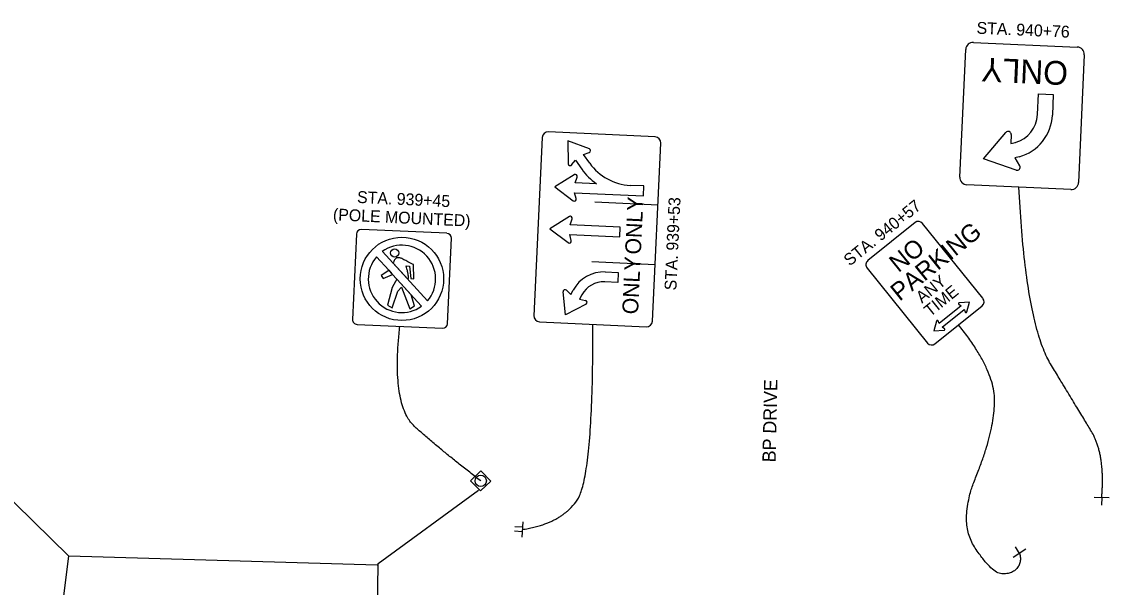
# Model space of a CAD drawing. Extents: x 1847379 to 1850904, y 217032 to 220169.
# Drawn here: x 1847990 to 1848218.9, y 218932.5 to 219051.5 of the extents above; entities that cross this region are included whole.
import ezdxf

# ---------------------------------------------------------------- set-up
doc = ezdxf.new("R2010")
doc.units = 0
for name, color, linetype in [('SG_X_Wiring', 7, 'Continuous'), ('SN_X_Foundation', 7, 'Continuous'), ('SN_X_Public', 7, 'Continuous'), ('SN_X_Text', 7, 'Continuous')]:
    doc.layers.add(name, color=color, linetype=linetype)

msp = doc.modelspace()

# ---------------------------------------------------------------- linework, layer by layer
at = {"layer": 'SG_X_Wiring'}
for p, q in [((1847999.88, 218939.03), (1847980.01, 218958.48)), ((1848065.02, 218937.49), (1848086.09, 218952.89)), ((1847991.33, 218868.98), (1847999.88, 218939.03)), ((1848064.78, 218937.13), (1847999.88, 218939.03)), ((1848063.94, 218866.48), (1848065.02, 218937.49))]:
    msp.add_line(p, q, dxfattribs=at)
at = {"layer": 'SN_X_Foundation'}
msp.add_lwpolyline([(1848086.54, 218952.73), (1848088.7, 218954.81), (1848086.62, 218956.97), (1848084.46, 218954.89)], close=True, dxfattribs=at)
msp.add_circle((1848086.58, 218954.85), 1.2, dxfattribs=at)
at = {"layer": 'SN_X_Public'}
for p, q in [((1848203.76, 219031.92), (1848203.96, 219036.29)), ((1848203.96, 219036.29), (1848207.08, 219036.15)), ((1848207.08, 219036.15), (1848206.88, 219031.78)), ((1848192.39, 219022.63), (1848197.1, 219028.17)), ((1848198.2, 219027.74), (1848198.13, 219025.81)), ((1848109.45, 219024.74), (1848104.91, 219026.4)), ((1848104.91, 219026.4), (1848104.98, 219021.57)), ((1848198.13, 219025.81), (1848199.09, 219026.07)), ((1848108.21, 219023.55), (1848109.43, 219023.95)), ((1848109.53, 219021.68), (1848108.21, 219023.55)), ((1848105.72, 219021.32), (1848106.51, 219022.35)), ((1848106.51, 219022.35), (1848107.83, 219020.47)), ((1848199.26, 219020.24), (1848192.39, 219022.63)), ((1848199.91, 219023.06), (1848198.95, 219022.8)), ((1848198.95, 219022.8), (1848200, 219021.17)), ((1848106.27, 219019.28), (1848102.16, 219016.73)), ((1848106.44, 219017.57), (1848106.88, 219018.78)), ((1848102.16, 219016.73), (1848106.01, 219013.81)), ((1848110.94, 219017.36), (1848106.44, 219017.57)), ((1848120.94, 219016.9), (1848118.03, 219017.03)), ((1848120.84, 219014.81), (1848120.94, 219016.9)), ((1848106.67, 219014.25), (1848106.34, 219015.49)), ((1848106.34, 219015.49), (1848120.84, 219014.81)), ((1848110.57, 219013.57), (1848123.89, 219012.95)), ((1848105.23, 219010.47), (1848101.13, 219007.92)), ((1848105.4, 219008.76), (1848105.84, 219009.97)), ((1848101.13, 219007.92), (1848104.98, 219004.99)), ((1848115.95, 219008.26), (1848105.4, 219008.76)), ((1848115.85, 219006.18), (1848115.95, 219008.26)), ((1848105.63, 219005.43), (1848105.3, 219006.68)), ((1848105.3, 219006.68), (1848115.85, 219006.18)), ((1848065.88, 219003.13), (1848075.37, 218992.73)), ((1848068.11, 219000.68), (1848068.21, 219000.57)), ((1848068.21, 219000.57), (1848071.28, 218997.21)), ((1848072.41, 219000.38), (1848072.39, 219000.38)), ((1848072.41, 219000.38), (1848072.39, 219000.38)), ((1848072.5, 218997.39), (1848072.41, 219000.38)), ((1848072.5, 218997.39), (1848072.41, 219000.38)), ((1848109.98, 219000.98), (1848123.3, 219000.36)), ((1848067.25, 218999.13), (1848065.65, 218998.05)), ((1848067.25, 218999.13), (1848065.65, 218998.05)), ((1848065.65, 218998.05), (1848066.03, 218997.45)), ((1848065.65, 218998.05), (1848066.03, 218997.45)), ((1848066.03, 218997.45), (1848068.03, 218998.27)), ((1848066.03, 218997.45), (1848068.03, 218998.27)), ((1848068.03, 218998.27), (1848067.88, 218998.44)), ((1848070.88, 219000.08), (1848071.61, 219000.02)), ((1848070.88, 219000.08), (1848071.61, 219000.02)), ((1848071.61, 219000.02), (1848071.87, 218997.47)), ((1848071.61, 219000.02), (1848071.87, 218997.47)), ((1848112.8, 218998.82), (1848115.5, 218998.69)), ((1848115.5, 218998.69), (1848115.41, 218996.61)), ((1848068.62, 218996.82), (1848067.97, 218995.56)), ((1848068.62, 218996.82), (1848067.97, 218995.56)), ((1848068.91, 218997.31), (1848068.62, 218996.82)), ((1848068.91, 218997.31), (1848068.62, 218996.82)), ((1848068.97, 218997.25), (1848068.91, 218997.31)), ((1848071.92, 218994.03), (1848068.97, 218997.25)), ((1848071.87, 218997.47), (1848072.5, 218997.39)), ((1848071.87, 218997.47), (1848072.5, 218997.39)), ((1848115.41, 218996.61), (1848112.7, 218996.74)), ((1848067.97, 218995.56), (1848066.96, 218991.82)), ((1848067.97, 218995.56), (1848066.96, 218991.82)), ((1848067.97, 218991.27), (1848069.17, 218994.74)), ((1848067.97, 218991.27), (1848069.17, 218994.74)), ((1848069.17, 218994.74), (1848069.93, 218995.61)), ((1848069.17, 218994.74), (1848069.93, 218995.61)), ((1848069.93, 218995.61), (1848071.69, 218991.02)), ((1848069.93, 218995.61), (1848071.69, 218991.02)), ((1848072.61, 218991.65), (1848071.92, 218994.03)), ((1848072.61, 218991.65), (1848071.92, 218994.03)), ((1848104.45, 218989.82), (1848103.92, 218994.63)), ((1848104.63, 218994.97), (1848105.53, 218994.05)), ((1848105.53, 218994.05), (1848106.03, 218994.98)), ((1848107.86, 218993.99), (1848107.37, 218993.06)), ((1848066.96, 218991.82), (1848067.97, 218991.27)), ((1848066.96, 218991.82), (1848067.97, 218991.27)), ((1848071.69, 218991.02), (1848072.61, 218991.65)), ((1848071.69, 218991.02), (1848072.61, 218991.65)), ((1848108.75, 218992.04), (1848104.45, 218989.82)), ((1848107.37, 218993.06), (1848108.63, 218992.82)), ((1848187.71, 218991.67), (1848183.08, 218987.94)), ((1848187.22, 218992.01), (1848187.72, 218991.68)), ((1848189.47, 218992.48), (1848187.31, 218992.34)), ((1848187.72, 218991.68), (1848187.71, 218991.67)), ((1848188.87, 218990.4), (1848189.47, 218992.48)), ((1848185.7, 218989.44), (1848185.7, 218989.44)), ((1848188.31, 218990.95), (1848188.52, 218990.39)), ((1848182.52, 218988.48), (1848181.92, 218986.4)), ((1848181.92, 218986.4), (1848184.08, 218986.55)), ((1848183.08, 218987.94), (1848182.87, 218988.5)), ((1848183.08, 218987.94), (1848183.09, 218987.94)), ((1848184.17, 218986.88), (1848183.67, 218987.21)), ((1848215.66, 218951.41), (1848218.85, 218951.33)), ((1848217.26, 218951.37), (1848217.21, 218949.77)), ((1848095.42, 218946.22), (1848095.23, 218943.03)), ((1848095.3, 218944.15), (1848093.7, 218944.24)), ((1848095.36, 218945.1), (1848093.76, 218945.2)), ((1848095.33, 218944.63), (1848095.33, 218944.63)), ((1848199.97, 218939.61), (1848199.1, 218940.95)), ((1848201.31, 218940.48), (1848198.63, 218938.74))]:
    msp.add_line(p, q, dxfattribs=at)
for points in [[(1848190.27, 219047.12), (1848212.12, 219046.14)], [(1848187.42, 219018.79), (1848188.64, 219045.63)], [(1848213.61, 219044.51), (1848212.4, 219017.66)], [(1848123.3, 219027.21), (1848100.83, 219028.26)], [(1848099.52, 219027.07), (1848097.77, 218989.61)], [(1848122.74, 218988.45), (1848124.49, 219025.91)], [(1848210.77, 219016.17), (1848188.91, 219017.16)], [(1848079.44, 219006.94), (1848061.46, 219007.75)], [(1848177.99, 219009.21), (1848168.06, 219001.21)], [(1848192.28, 218993.27), (1848179.57, 219009.04)], [(1848060.42, 219006.79), (1848059.61, 218988.81)], [(1848079.59, 218987.91), (1848080.4, 219005.89)], [(1848064.63, 219001.99), (1848067.21, 218999.17), (1848067.88, 218998.45), (1848067.88, 218998.44)], [(1848068.21, 219000.57), (1848068.21, 219000.57)], [(1848067.88, 218998.44), (1848067.25, 218999.13), (1848067.25, 218999.13)], [(1848067.88, 218998.44), (1848068.97, 218997.25), (1848072.51, 218993.38), (1848074.14, 218991.6)], [(1848167.89, 218999.62), (1848180.6, 218983.86)], [(1848182.18, 218983.69), (1848192.11, 218991.69)], [(1848183.67, 218987.21), (1848188.3, 218990.94)], [(1848060.56, 218987.77), (1848078.55, 218986.96)], [(1848098.96, 218988.31), (1848121.43, 218987.26)]]:
    msp.add_lwpolyline(points, dxfattribs=at)
for centre, radius in [((1848070, 218997.36), 8.77), ((1848068.47, 219002.81), 0.864)]:
    msp.add_circle(centre, radius, dxfattribs=at)
for centre, radius, start, end in [((1848190.2, 219045.56), 1.56, 87.4125, 177.4125), ((1848212.05, 219044.58), 1.56, 357.4125, 87.4125), ((1848197.41, 219032.2), 6.35, 285.2738, 357.4125), ((1848197.41, 219032.2), 9.48, 285.2699, 357.4125), ((1848100.77, 219027.02), 1.25, 87.3236, 177.3236), ((1848197.58, 219027.77), 0.625, 357.8864, 139.6582), ((1848123.24, 219025.96), 1.25, 357.3236, 87.3236), ((1848109.3, 219024.35), 0.417, 287.9475, 69.8256), ((1848105.39, 219021.58), 0.417, 180.7931, 322.6712), ((1848118.54, 219028.06), 11.04, 215.3093, 267.3236), ((1848199.47, 219020.83), 0.625, 250.8471, 32.6189), ((1848106.49, 219018.93), 0.417, 339.9618, 121.8399), ((1848118.54, 219028.06), 13.12, 215.3093, 234.5981), ((1848188.98, 219018.72), 1.56, 177.4125, 267.4125), ((1848210.84, 219017.73), 1.56, 267.4125, 357.4125), ((1848106.27, 219014.14), 0.417, 232.8074, 14.6855), ((1848105.45, 219010.11), 0.417, 339.9618, 121.8399), ((1848178.7, 219008.33), 1.12, 38.8676, 128.8676), ((1848061.42, 219006.75), 1, 87.4245, 177.4245), ((1848079.4, 219005.94), 1, 357.4245, 87.4245), ((1848105.23, 219005.32), 0.417, 232.8074, 14.6855), ((1848070, 218997.36), 7.09, 319.2436, 125.5959), ((1848070, 218997.36), 7.09, 139.2725, 305.6725), ((1848070, 218997.36), 7.09, 139.2725, 305.6725), ((1848168.77, 219000.33), 1.12, 128.8676, 218.8676), ((1848112.46, 218991.53), 7.29, 87.3236, 151.8409), ((1848112.46, 218991.53), 5.21, 87.3236, 151.8409), ((1848104.33, 218994.67), 0.417, 44.4791, 186.3572), ((1848108.55, 218992.41), 0.417, 297.3247, 79.2028), ((1848187.32, 218992.16), 0.182, 93.7884, 236.5054), ((1848191.4, 218992.56), 1.12, 308.8676, 38.8676), ((1848099.02, 218989.56), 1.25, 177.3236, 267.3236), ((1848188.69, 218990.45), 0.182, 201.2298, 343.9469), ((1848060.61, 218988.77), 1, 177.4245, 267.4245), ((1848078.59, 218987.96), 1, 267.4245, 357.4245), ((1848121.49, 218988.51), 1.25, 267.3236, 357.3236), ((1848182.7, 218988.43), 0.182, 21.2298, 163.9469), ((1848184.07, 218986.73), 0.182, 273.7884, 56.5054), ((1848181.48, 218984.56), 1.12, 218.8676, 308.8676)]:
    msp.add_arc(centre, radius, start, end, dxfattribs=at)
for points, degree in [([(1848217.26, 218951.37), (1848218.07, 218960.43), (1848211.9, 218970.55), (1848201.25, 218988.11), (1848199.84, 219016.66)], 2), ([(1848072.39, 219000.38), (1848071.53, 219000.81), (1848070.17, 219001.51), (1848069.67, 219001.76), (1848069.5, 219001.8), (1848069.33, 219001.81), (1848068.93, 219001.83), (1848068.41, 219001.38), (1848068.23, 219000.95), (1848068.11, 219000.68)], 3), ([(1848072.39, 219000.38), (1848071.53, 219000.81), (1848070.17, 219001.51), (1848069.67, 219001.76), (1848069.5, 219001.8), (1848069.33, 219001.81), (1848068.93, 219001.83), (1848068.41, 219001.38), (1848068.23, 219000.95), (1848068.11, 219000.68)], 3), ([(1848071.28, 218997.21), (1848071.32, 218997.28), (1848071.39, 218997.48), (1848071.38, 218997.94), (1848071.31, 218998.36), (1848071.15, 218999.09), (1848071.02, 218999.6), (1848070.88, 219000.08)], 3), ([(1848071.28, 218997.21), (1848071.32, 218997.28), (1848071.39, 218997.48), (1848071.38, 218997.94), (1848071.31, 218998.36), (1848071.15, 218999.09), (1848071.02, 218999.6), (1848070.88, 219000.08)], 3), ([(1848086.58, 218954.85), (1848077.73, 218961.68), (1848067.7, 218970.82), (1848069.55, 218987.36)], 2), ([(1848095.33, 218944.63), (1848103.41, 218945.81), (1848110.27, 218955.68), (1848110.2, 218987.78)], 2), ([(1848199.97, 218939.61), (1848200.51, 218937.81), (1848198.45, 218935.25), (1848194.27, 218935.3), (1848186.95, 218946.24), (1848194.64, 218965.14), (1848194.81, 218978.11), (1848187.15, 218987.69)], 2)]:
    msp.add_open_spline(points, degree=degree, dxfattribs=at)

# ---------------------------------------------------------------- texts
for s, height, rotation, p in [('STA. 940+76', 2.5, 357.4806, (1848190.89, 219048.95)), ('ONLY', 5, 177.4125, (1848210.27, 219043.09)), ('ONLY', 3.333, 87.3236, (1848120.27, 219002.43)), ('STA. 939+53', 2.5, 87.3918, (1848127.75, 218994.9)), ('STA. 940+57', 2.5, 38.9358, (1848164.23, 218999.93)), ('PARKING', 3.75, 38.8676, (1848174.73, 218992.53)), ('NO', 3.75, 38.8676, (1848174.48, 218998.55)), ('ONLY', 3.333, 87.3236, (1848119.68, 218989.84)), ('ANY', 2.5, 38.8676, (1848179.44, 218992.11)), ('TIME', 2.5, 38.8676, (1848181.15, 218989.28)), ('BP DRIVE', 2.8, 88.7843, (1848148.65, 218958.74))]:
    msp.add_text(s, height=height, rotation=rotation, dxfattribs=at).set_placement(p)
at = {"layer": 'SN_X_Text'}
for s, p in [('STA. 939+45', (1848060.51, 219013.36)), ('(POLE MOUNTED)', (1848055.44, 219009.7))]:
    msp.add_text(s, height=2.5, rotation=357.313, dxfattribs=at).set_placement(p)

doc.saveas('drawing.dxf')
